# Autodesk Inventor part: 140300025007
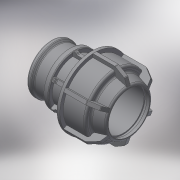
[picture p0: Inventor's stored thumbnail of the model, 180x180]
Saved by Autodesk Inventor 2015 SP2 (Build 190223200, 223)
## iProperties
Created: 2017-08
Part Number: 140300025007
Material: Generic
Description: PLASSON L.14 FEMALE ADAPTOR (SILVER) 25-3/4"
Document SubType Name: Modeling
Designer: KIM
Density: 1 g/cm^3
Appearance: Default
Author: KIM
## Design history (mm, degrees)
derived "140300.ipt"
feature "Solid1::140300.ipt"
tag "TaggingFeature1"
body "Solid1"
other parameters: "d1" = 25, "d2" = 54, "d4" = 15 deg, "d5" = 35.64, "d6" = 11.7612, "d9" = 24.117, "d11" = 31.3521, "d12" = 28.9404, "d13" = 33.7638, "d14" = 19, "d16" = 25.5, "d17" = 2.7, "d18" = 75, "d19" = 5.7, "d20" = 135 deg, "d21" = 5.7, "d22" = 28.9404, "d23" = 22.5, "d24" = 2.7, "d25" = 45, "d26" = 37.5, "d27" = 2.7, "d28" = 135 deg, "d29" = 1.62, "d31" = 1.25, "d44" = 0.5, "d45" = 0.75, "d46" = 150 deg, "d49" = 2.5, "d50" = 0, "d51" = 0.5, "d52" = 1, "d53" = 45 deg, "d55" = 6.804, "d56" = 2.5, "d57" = 0, "d58" = 0.75, "d61" = 360 deg, "d_" = 25, "G_" = 24.117, "H_" = 75, "l_" = 54, "l_2" = 19, "d54" = 17.01
